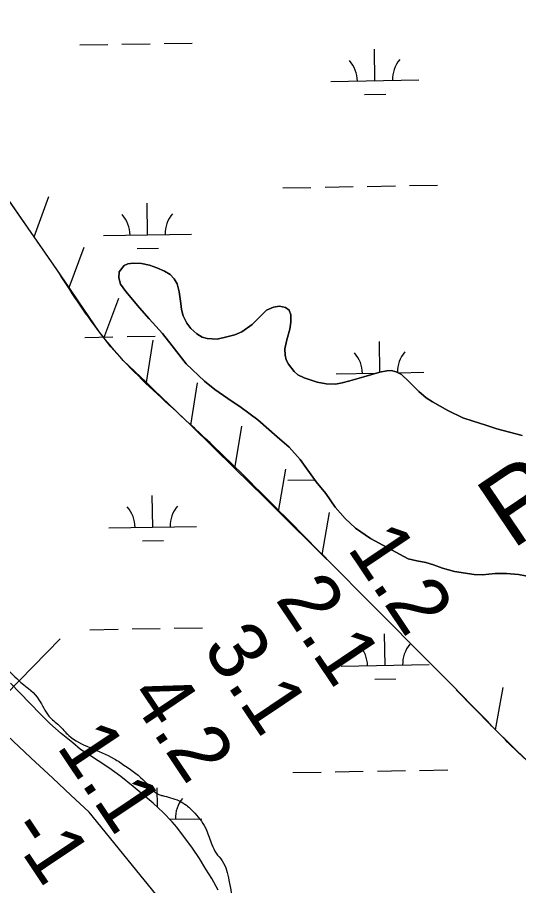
# Model space of a CAD drawing. Extents: x 3892998 to 3931244, y 278583 to 304547.
# Drawn here: x 3911568 to 3912138, y 293140 to 294128 of the extents above; entities that cross this region are included whole.
import ezdxf

# ---------------------------------------------------------------- set-up
doc = ezdxf.new("R2010")
doc.units = 0
for name, color, linetype in [('V-RIVR-EDGE', 7, 'Continuous'), ('V-RIVR-RANG', 7, 'Continuous'), ('V-RIVR-RANG-IDEN', 7, 'Continuous'), ('V-RRAP-FSHR', 7, 'Continuous'), ('V-TOPO-SHOR', 7, 'Continuous'), ('V-TOPO-WATR', 7, 'Continuous'), ('V-UTIL-LINE', 7, 'Continuous'), ('V-WETL-SWMP', 7, 'Continuous')]:
    doc.layers.add(name, color=color, linetype=linetype)

msp = doc.modelspace()

# ---------------------------------------------------------------- linework, layer by layer
at = {"layer": 'V-RIVR-EDGE'}
for points in [[(3909783.09, 295866.63), (3909800.66, 295843.98), (3909812.93, 295827.98), (3909826.51, 295806.34), (3909841.42, 295785.35), (3909858.31, 295759.37), (3909870.24, 295740.05), (3909885.82, 295720.73), (3909893.46, 295717.72), (3909900.11, 295717.7), (3909908.43, 295721.34), (3909917.08, 295722.31), (3909926.72, 295720.63), (3909934.68, 295712.63), (3909944.61, 295694.31), (3909956.87, 295675.33), (3909970.78, 295655.01), (3909981.06, 295641.35), (3909987.34, 295626.37), (3909992.62, 295609.73), (3909998.9, 295595.41), (3910003.21, 295587.42), (3910002.19, 295579.78), (3909995.48, 295557.51), (3909984.14, 295542.25), (3909975.8, 295533.62), (3909959.5, 295528.67), (3909954.17, 295524.69), (3909952.49, 295520.38), (3909952.82, 295516.72), (3909956.8, 295513.05), (3909961.1, 295505.72), (3909960.75, 295495.75), (3909955.73, 295483.79), (3909949.06, 295475.82), (3909943.39, 295469.19), (3909939.71, 295462.21), (3909939.37, 295457.23), (3909939.35, 295450.24), (3909940.68, 295448.58), (3909945.99, 295445.9), (3909952.31, 295444.56), (3909957.61, 295438.56), (3909959.92, 295429.24), (3909962.22, 295419.26), (3909968.52, 295411.93), (3909977.16, 295409.25), (3909984.46, 295402.91), (3909993.74, 295388.59), (3909996.37, 295377.28), (3909993.68, 295366.98), (3909987.67, 295356.02), (3909986.67, 295353.36), (3909987.32, 295349.37), (3909993.29, 295342.7), (3910005.91, 295335.02), (3910014.55, 295332.67), (3910021.53, 295332.66), (3910027.84, 295329.98), (3910041.1, 295312.99), (3910056.01, 295290.67), (3910079.54, 295258.36), (3910099.09, 295232.04), (3910120.64, 295203.72), (3910140.54, 295184.05), (3910162.73, 295147.42), (3910185.26, 295114.77), (3910212.11, 295076.8), (3910225.37, 295062.8), (3910233, 295056.46), (3910237, 295056.78), (3910260.95, 295062.04), (3910322.87, 295089.16), (3910330.2, 295092.8), (3910331.86, 295093.13), (3910334.85, 295093.12), (3910344.48, 295087.44), (3910346.81, 295087.44), (3910348.48, 295089.1), (3910343.86, 295106.4), (3910343.88, 295113.38), (3910346.55, 295119.03), (3910349.22, 295121.35), (3910352.88, 295122.01), (3910354.87, 295121.67), (3910356.2, 295119.34), (3910359.17, 295110.68), (3910367.46, 295103.02), (3910381.41, 295093.67), (3910395.35, 295085.32), (3910404.65, 295078.32), (3910418.59, 295068.31), (3910432.22, 295065.61), (3910442.83, 295055.61), (3910459.44, 295049.25), (3910467.08, 295042.91), (3910469.05, 295035.92), (3910475.65, 295012.63), (3910478.94, 294999.99), (3910484.25, 294994.65), (3910493.53, 294981.99), (3910494.17, 294971.02), (3910493.48, 294962.71), (3910485.48, 294955.08), (3910479.8, 294945.45), (3910478.46, 294939.47), (3910478.45, 294934.15), (3910482.44, 294934.14), (3910487.42, 294932.79), (3910491.4, 294928.79), (3910494.05, 294924.13), (3910493.03, 294916.82), (3910496.36, 294916.14), (3910502.68, 294915.8), (3910510.66, 294918.77), (3910515.32, 294919.09), (3910521.63, 294914.75), (3910528.25, 294904.76), (3910533.84, 294879.14), (3910536.15, 294868.83), (3910539.77, 294853.85), (3910546.37, 294836.21), (3910553.65, 294821.56), (3910561.94, 294811.23), (3910569.22, 294797.25), (3910578.5, 294783.92), (3910593.43, 294768.59), (3910609.36, 294755.92), (3910620.64, 294746.58), (3910629.59, 294736.58), (3910633.22, 294723.27), (3910633.51, 294704.98), (3910640.45, 294687.67), (3910655.34, 294658.37), (3910658.96, 294645.06), (3910658.58, 294624.44), (3910656.89, 294614.47), (3910650.55, 294604.18), (3910648.87, 294596.53), (3910653.17, 294587.88), (3910655.47, 294576.23), (3910652.12, 294567.93), (3910652.11, 294561.61), (3910655.74, 294551.96), (3910653.36, 294529.35), (3910654.64, 294512.05), (3910656.92, 294490.77), (3910662.86, 294473.46), (3910678.76, 294446.15), (3910695.33, 294425.16), (3910704.29, 294415.83), (3910727.49, 294385.84), (3910746.72, 294363.52), (3910775.56, 294325.54), (3910789.15, 294306.88), (3910800.09, 294294.55), (3910807.37, 294280.9), (3910822.95, 294258.91), (3910842.83, 294232.92), (3910870.69, 294199.93), (3910889.91, 294176.28), (3910900.18, 294159.96), (3910907.48, 294152.29), (3910954.23, 294096.31), (3910972.8, 294076.98), (3910990.73, 294066.96), (3910998.38, 294065.94), (3911008.03, 294068.24), (3911013.02, 294070.23), (3911023.33, 294070.87), (3911029.98, 294071.51), (3911038.98, 294076.48), (3911042.63, 294076.8), (3911044.95, 294073.47), (3911037.59, 294053.54), (3911030.9, 294037.26), (3911029.21, 294027.95), (3911029.86, 294022.3), (3911033.49, 294009.32), (3911043.41, 293989.01), (3911049.71, 293980.68), (3911065.96, 293963.68), (3911085.84, 293933.04), (3911095.77, 293913.73), (3911115.01, 293894.06), (3911136.58, 293876.05), (3911169.13, 293860.68), (3911193.06, 293855.3), (3911217.66, 293853.9), (3911241.28, 293856.51), (3911264.57, 293860.77), (3911275.54, 293860.41), (3911285.5, 293855.73), (3911306.41, 293839.05), (3911330.64, 293821.37), (3911338.6, 293813.04), (3911343.57, 293806.04), (3911345.55, 293797.39), (3911348.15, 293772.44), (3911349.43, 293752.49), (3911353.06, 293742.84), (3911359.35, 293730.18), (3911360, 293725.86), (3911358.28, 293702.92), (3911357.93, 293694.94), (3911358.9, 293682.63), (3911359.2, 293669.33), (3911359.16, 293655.7), (3911363.77, 293633.74), (3911372.03, 293613.43), (3911386.6, 293588.79), (3911397.21, 293575.79), (3911412.13, 293557.8), (3911430.05, 293545.45), (3911442.34, 293538.44), (3911446.32, 293532.44), (3911447.28, 293520.14), (3911450.58, 293509.49), (3911455.55, 293500.83), (3911461.85, 293492.5), (3911478.78, 293482.15), (3911498.68, 293462.48), (3911520.89, 293434.49), (3911530.83, 293418.51), (3911540.11, 293404.18), (3911553.37, 293389.19), (3911571.62, 293371.52)], [(3911571.62, 293371.52), (3911592.19, 293351.85), (3911603.45, 293333.2), (3911615.06, 293322.53), (3911626, 293311.19), (3911649.91, 293297.5), (3911677.48, 293284.8), (3911690.43, 293276.45), (3911713, 293258.44), (3911728.59, 293244.1), (3911732.58, 293242.76), (3911741.88, 293240.41), (3911751.52, 293236.73), (3911759.82, 293231.72), (3911769.44, 293222.72), (3911782.69, 293203.4), (3911788.64, 293187.09), (3911793.6, 293177.43), (3911800.56, 293168.44), (3911808.16, 293146.47), (3911813.08, 293117.86), (3911816.32, 293083.27), (3911812.59, 293056.34), (3911805.92, 293046.72), (3911791.91, 293031.12)]]:
    msp.add_spline(points, degree=3, dxfattribs=at)
at = {"layer": 'V-RRAP-FSHR'}
for p, q in [((3911586.6, 293878.53), (3911603.5, 293924.35)), ((3911626.37, 293820.93), (3911643.57, 293866.63)), ((3911665.89, 293763.15), (3911683.09, 293808.85)), ((3911714.36, 293712.73), (3911721.86, 293760.98)), ((3911764.88, 293664.28), (3911772.35, 293712.54)), ((3911814.69, 293615.1), (3911822.78, 293663.25)), ((3911864.52, 293565.94), (3911872.8, 293614.06)), ((3911914.23, 293516.65), (3911922.51, 293564.77)), ((3912111.3, 293317.75), (3912120.11, 293365.78))]:
    msp.add_line(p, q, dxfattribs=at)
for points in [[(3911612.45, 293841.27), (3911391.45, 294159.85), (3911136.35, 294536.57), (3910622.45, 295297.48), (3910313.12, 295761.47), (3909557.44, 296871.45), (3909043.37, 297649.25), (3908973.22, 297752.54), (3908945.72, 297766.03), (3908677.05, 297883.62)], [(3911586.6, 293878.53), (3911546.7, 293936.05)], [(3911626.37, 293820.93), (3911612.45, 293841.27), (3911586.6, 293878.53)], [(3911666.23, 293763.4), (3911661.12, 293770.12), (3911636.79, 293805.7), (3911626.37, 293820.93)], [(3911714.36, 293712.73), (3911688.06, 293737.99), (3911673.81, 293753.42), (3911666.23, 293763.4)], [(3911814.69, 293615.1), (3911764.79, 293664.19), (3911757.65, 293671.21), (3911722.86, 293704.58), (3911714.36, 293712.73)], [(3911864.52, 293565.94), (3911848.13, 293582.2), (3911814.69, 293615.1)], [(3911919.36, 293511.57), (3911914.23, 293516.65), (3911864.52, 293565.94)], [(3912111.33, 293317.79), (3912107.21, 293321.9), (3912066.47, 293363.21)], [(3912162.12, 293269.67), (3912148.71, 293280.96), (3912127.84, 293301.33), (3912111.33, 293317.79)]]:
    msp.add_lwpolyline(points, dxfattribs=at)
msp.add_spline([(3912490.43, 293178.4), (3912453.52, 293152.1), (3912417.98, 293147.6), (3912381.66, 293157.91), (3912285.65, 293193.67), (3912195.37, 293245.01), (3912148.71, 293280.96), (3912107.21, 293321.9), (3911938.25, 293492.83), (3911757.65, 293671.21), (3911688.06, 293737.99), (3911661.12, 293770.12), (3911612.45, 293841.27)], degree=3, dxfattribs=at)
at = {"layer": 'V-TOPO-SHOR'}
for points in [[(3912011.93, 293512.18), (3911969.05, 293535.36), (3911951.96, 293547.22), (3911940.32, 293558.03), (3911928.86, 293571.12), (3911918.28, 293586.38), (3911907.42, 293599.77), (3911888.96, 293625.18), (3911876.71, 293639.35), (3911862.89, 293651.03), (3911841.1, 293670.29), (3911822.22, 293684.32), (3911806.82, 293694.41), (3911792.02, 293704.8), (3911780.19, 293714.42), (3911759.69, 293733.98), (3911743.44, 293754.66), (3911732.77, 293768.64), (3911717.43, 293785.26), (3911706.57, 293797.86), (3911691.03, 293816.36), (3911684.94, 293824.73), (3911682.82, 293832.04), (3911683.47, 293838.57), (3911689.06, 293845.92), (3911693.31, 293847.83), (3911699.43, 293848.66), (3911708.83, 293848.12), (3911717.65, 293846.4), (3911726.08, 293843.28), (3911734.9, 293839.38), (3911741.46, 293835.66), (3911745.94, 293830.84), (3911749.24, 293824.93), (3911751.47, 293816.14), (3911753.53, 293802.5), (3911754.37, 293795.78), (3911756.19, 293788.67), (3911760.3, 293780.18), (3911764.88, 293774.28), (3911771.75, 293768.19), (3911777.81, 293764.36), (3911783.45, 293762.72), (3911794.83, 293762.2), (3911805.8, 293764.64), (3911814.88, 293767.17), (3911822.78, 293770.28), (3911834.4, 293778.96), (3911842.85, 293787.12), (3911850.92, 293794.99), (3911858.81, 293798.4), (3911865.53, 293799.73), (3911872.56, 293798.19), (3911876.44, 293794.95), (3911878.55, 293789.62), (3911878.7, 293781.41), (3911877.27, 293773.49), (3911874.07, 293761.3), (3911871.66, 293751.29), (3911872.1, 293743.88), (3911873.33, 293738.44), (3911875.93, 293733.61), (3911882.31, 293725.15), (3911886.39, 293721.71), (3911893.83, 293717.99), (3911901.46, 293715.57), (3911908.3, 293713.34), (3911918.8, 293711.12), (3911929.29, 293711.09), (3911937, 293712.43), (3911945.79, 293714.56), (3911961.39, 293719.1), (3911979.55, 293724.56), (3911987.85, 293726.19), (3911992.5, 293726.42), (3911998.25, 293724.97), (3912004.2, 293722.04), (3912012.66, 293714.08), (3912024.21, 293702.58), (3912032.56, 293695.51), (3912039.51, 293690.9), (3912057.18, 293681.02), (3912073.95, 293672.51), (3912085.75, 293668.73), (3912100.12, 293664.07), (3912112.9, 293660.19), (3912141.64, 293652.55)], [(3912153.22, 293491.19), (3912137.47, 293494.16), (3912123.62, 293495.45), (3912110.75, 293495.38), (3912096.62, 293494.1), (3912087.12, 293494.24), (3912064.54, 293497.66), (3912050.97, 293501.54), (3912040.85, 293505.23), (3912031.84, 293507.95), (3912021.64, 293510.06), (3912011.93, 293512.18)]]:
    msp.add_lwpolyline(points, dxfattribs=at)
at = {"layer": 'V-TOPO-WATR'}
msp.add_lwpolyline([(3911904.12, 292910.08), (3911649.21, 293223.89), (3911628.55, 293243.4), (3911607.76, 293262.76), (3911582.98, 293285.59), (3911556.15, 293311.05), (3911529.84, 293337.02), (3911504.32, 293363.77), (3911479.31, 293391.02), (3911454.7, 293418.66), (3911430.09, 293446.31), (3911405.5, 293473.98), (3911380.92, 293501.64), (3911346.28, 293540.63), (3911304.64, 293588.02), (3911263.35, 293635.7), (3911222.57, 293683.83), (3911182.13, 293732.24), (3911126.81, 293799.21), (3911108.41, 293821.68), (3911090.16, 293844.27), (3911072.13, 293867.03), (3911054.23, 293889.9), (3910800.21, 294217.61)], dxfattribs=at)
at = {"layer": 'V-UTIL-LINE'}
msp.add_lwpolyline([(3909289.24, 291686.81), (3909873.21, 292040.74), (3910448.35, 292403.51), (3910704.94, 292589.32), (3911244.68, 293040.58), (3911616.3, 293421.05)], dxfattribs=at)
at = {"layer": 'V-WETL-SWMP'}
for p, q in [((3911638.55, 294096.81), (3911670.54, 294097.37)), ((3911686.54, 294097.64), (3911718.53, 294098.2)), ((3911734.53, 294098.47), (3911766.53, 294099.03)), ((3911974.14, 294056.19), (3911973.52, 294092.18)), ((3911924.15, 294055.32), (3912024.14, 294057.05)), ((3911962.41, 294040.55), (3911986.41, 294040.96)), ((3911869.39, 293934.28), (3911901.39, 293934.84)), ((3911917.39, 293935.11), (3911949.38, 293935.67)), ((3911965.38, 293935.94), (3911997.37, 293936.5)), ((3912013.37, 293936.78), (3912045.37, 293937.33)), ((3911715.7, 293880.87), (3911715.08, 293916.87)), ((3911665.71, 293880.01), (3911765.69, 293881.74)), ((3911703.97, 293865.24), (3911727.97, 293865.65)), ((3911644.3, 293764.19), (3911676.3, 293764.74)), ((3911692.3, 293765.02), (3911724.29, 293765.57)), ((3911979.88, 293724.62), (3911979.28, 293759.55)), ((3912000.39, 293723.91), (3912029.89, 293724.43)), ((3911929.91, 293722.69), (3911976, 293723.49)), ((3911875.15, 293601.66), (3911905.66, 293602.19)), ((3911721.46, 293548.25), (3911720.84, 293584.24)), ((3911671.47, 293547.38), (3911771.45, 293549.11)), ((3911709.73, 293532.61), (3911733.73, 293533.03)), ((3911650.06, 293431.56), (3911682.06, 293432.12)), ((3911698.05, 293432.39), (3911730.05, 293432.95)), ((3911746.05, 293433.22), (3911778.04, 293433.78)), ((3911985.66, 293390.93), (3911985.04, 293426.93)), ((3911935.67, 293390.07), (3912035.65, 293391.8)), ((3911973.93, 293375.3), (3911997.92, 293375.71)), ((3911880.91, 293269.03), (3911912.9, 293269.59)), ((3911928.9, 293269.86), (3911960.9, 293270.42)), ((3911976.89, 293270.69), (3912008.89, 293271.25)), ((3912024.89, 293271.52), (3912056.88, 293272.08)), ((3911726.98, 293229.44), (3911726.59, 293251.62)), ((3911740.7, 293215.86), (3911777.21, 293216.49))]:
    msp.add_line(p, q, dxfattribs=at)
for points in [[(3911875.93, 293733.61), (3911873.33, 293738.44), (3911872.1, 293743.88), (3911871.66, 293751.29), (3911874.08, 293761.3), (3911877.26, 293773.49), (3911878.7, 293781.41), (3911878.55, 293789.62), (3911876.44, 293794.95), (3911872.56, 293798.19), (3911865.53, 293799.73), (3911858.81, 293798.4), (3911850.92, 293794.99), (3911842.85, 293787.12), (3911834.4, 293778.96), (3911822.78, 293770.28), (3911814.88, 293767.17), (3911805.8, 293764.64), (3911794.83, 293762.2), (3911783.45, 293762.72), (3911777.81, 293764.37), (3911771.75, 293768.19), (3911764.88, 293774.28), (3911760.3, 293780.18), (3911756.19, 293788.67), (3911754.36, 293795.78), (3911753.53, 293802.5), (3911751.47, 293816.14), (3911749.24, 293824.93), (3911745.94, 293830.84), (3911741.46, 293835.66), (3911734.9, 293839.38), (3911726.08, 293843.28), (3911717.65, 293846.4), (3911708.83, 293848.12), (3911699.43, 293848.66), (3911693.31, 293847.83), (3911689.06, 293845.92), (3911683.47, 293838.57), (3911682.82, 293832.04), (3911684.94, 293824.73), (3911691.03, 293816.36), (3911706.57, 293797.86), (3911717.43, 293785.26), (3911732.77, 293768.64), (3911743.44, 293754.66), (3911759.69, 293733.98), (3911780.19, 293714.42), (3911792.02, 293704.8), (3911806.83, 293694.41), (3911822.22, 293684.32), (3911841.1, 293670.29), (3911862.89, 293651.03), (3911876.71, 293639.35), (3911888.96, 293625.18), (3911907.42, 293599.77), (3911918.29, 293586.38), (3911928.87, 293571.11), (3911940.32, 293558.03), (3911951.96, 293547.22), (3911969.05, 293535.36), (3912011.93, 293512.18), (3912021.64, 293510.06), (3912031.84, 293507.95)], [(3912141.64, 293652.55), (3912112.9, 293660.19), (3912100.12, 293664.07), (3912085.75, 293668.73), (3912073.95, 293672.52), (3912057.18, 293681.02), (3912039.51, 293690.9), (3912032.56, 293695.51), (3912024.21, 293702.58), (3912012.66, 293714.08), (3912004.2, 293722.04), (3911998.25, 293724.97), (3911992.5, 293726.42), (3911987.85, 293726.19), (3911979.55, 293724.56), (3911961.39, 293719.1), (3911945.79, 293714.56), (3911936.99, 293712.43), (3911929.29, 293711.09), (3911918.8, 293711.13), (3911908.3, 293713.34), (3911901.46, 293715.57), (3911893.83, 293717.99), (3911886.39, 293721.71), (3911882.31, 293725.15), (3911875.93, 293733.61)], [(3912031.84, 293507.95), (3912040.85, 293505.23), (3912050.97, 293501.54), (3912064.54, 293497.66), (3912087.12, 293494.24), (3912096.62, 293494.1), (3912110.75, 293495.38), (3912123.61, 293495.46), (3912137.47, 293494.16), (3912153.22, 293491.19)], [(3911796.03, 293135.1), (3911788.55, 293148.65), (3911781.98, 293159.26), (3911774.62, 293171.23), (3911766.66, 293183.11), (3911748.78, 293206.75), (3911743.62, 293212.92), (3911733.2, 293223.4), (3911722, 293234.27), (3911710.51, 293243.66), (3911699.22, 293253.05), (3911685.35, 293264.5), (3911671.5, 293274.36), (3911647.16, 293290.28), (3911639.24, 293295.25), (3911630.52, 293302.69), (3911617.55, 293313.55), (3911604.57, 293324.9), (3911594.16, 293335.18), (3911581.36, 293348.21), (3911559.84, 293370.64)]]:
    msp.add_lwpolyline(points, dxfattribs=at)
for centre, start, end in [((3912029.37, 294057.62), 140.21988, 181.76354), ((3911918.9, 294055.7), 0.21988, 41.76354), ((3911660.46, 293880.39), 0.21988, 41.76354), ((3911770.93, 293882.3), 140.21988, 181.76354), ((3911924.66, 293723.08), 0.21988, 41.76354), ((3912035.13, 293724.99), 140.21988, 181.34701), ((3911666.22, 293547.77), 0.21988, 41.76354), ((3911776.69, 293549.68), 140.21988, 181.76354), ((3911930.42, 293390.45), 0.21988, 41.76354), ((3912040.88, 293392.37), 140.21988, 181.76354), ((3911782.44, 293217.05), 140.21988, 181.76354)]:
    msp.add_arc(centre, 35.25, start, end, dxfattribs=at)

# ---------------------------------------------------------------- texts
at = {"layer": 'V-RIVR-RANG'}
for s, p in [('1.2', (3911941.75, 293524.14)), ('2.1', (3911860.13, 293466.31)), ('3.1', (3911777.18, 293410.46)), ('4.2', (3911692.91, 293356.58)), ('1.1', (3911611.28, 293298.75)), ('-1', (3911554.91, 293203.23))]:
    msp.add_text(s, height=67, rotation=303.81833, dxfattribs=at).set_placement(p)
at = {"layer": 'V-RIVR-RANG-IDEN'}
msp.add_text('R-11.6', height=83, rotation=33.9553, dxfattribs=at).set_placement((3912130.01, 293522.08))

doc.saveas('drawing.dxf')
